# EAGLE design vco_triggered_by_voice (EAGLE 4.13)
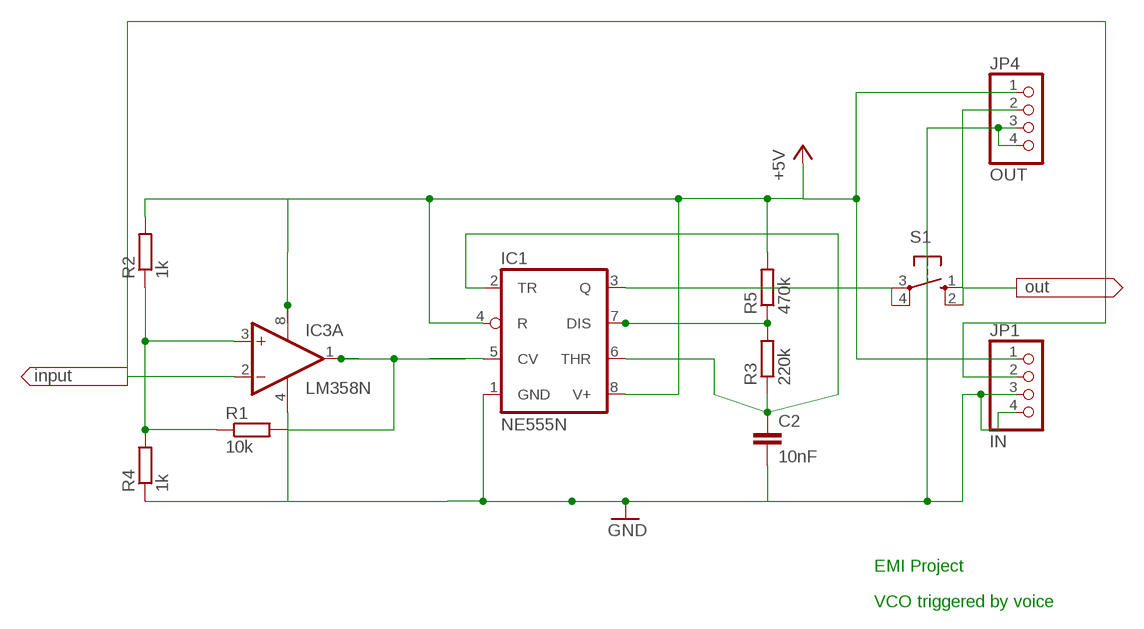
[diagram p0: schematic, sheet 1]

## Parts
C2  10nF  C-EU025-024X044  [C025-024X044]
IC1  NE555N  [DIL08]
IC3  LM358N  [DIL08]
JP1  IN  PINHD-1X4  [1X04]
JP4  OUT  PINHD-1X4  [1X04]
R1  10k  R-EU_0204/7  [0204/7]
R2  1k  R-EU_0204/7  [0204/7]
R3  220k  R-EU_0207/7  [0207/7]
R4  1k  R-EU_0204/7  [0204/7]
R5  470k  R-EU_0207/7  [0207/7]
S1  10-XX  [B3F-10XX]

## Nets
+5V: IC1.4(R) IC1.8(V+) IC3.8(P:V+) JP1.1 JP4.1 R2.2 R5.2
GND: C2.2 IC1.1(GND) IC3.4(P:V-) JP1.3 JP1.4 JP4.3 JP4.4 R4.1
N$1: IC3.3(A:+IN) R1.1 R2.1 R4.2
N$2: C2.1 IC1.2(TR) IC1.6(THR) R3.1
N$3: JP4.2 S1.1(S) S1.2(S1)
N$4: IC1.3(Q) S1.3(P) S1.4(P1)
N$6: IC1.7(DIS) R3.2 R5.1
N$7: IC3.2(A:-IN) JP1.2
N$9: IC1.5(CV) IC3.1(A:OUT) R1.2
Unconnected: IC3.5(B:+IN) IC3.6(B:-IN) IC3.7(B:OUT)

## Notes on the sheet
- EMI Project
- VCO triggered by voice

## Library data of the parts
C2 = rcl:C-EU: CAPACITOR, European symbol
IC1 = linear:*555: TIMER
IC3 = linear:LM358: OP AMP also LM158; LM258; LM2904 Source: http://cache.national.com/ds/LM/LM158.pdf
JP1 JP4 = pinhead:PINHD-1X4: PIN HEADER
R1-R5 = rcl:R-EU_: RESISTOR, European symbol
S1 = switch-omron:10-XX: OMRON SWITCH

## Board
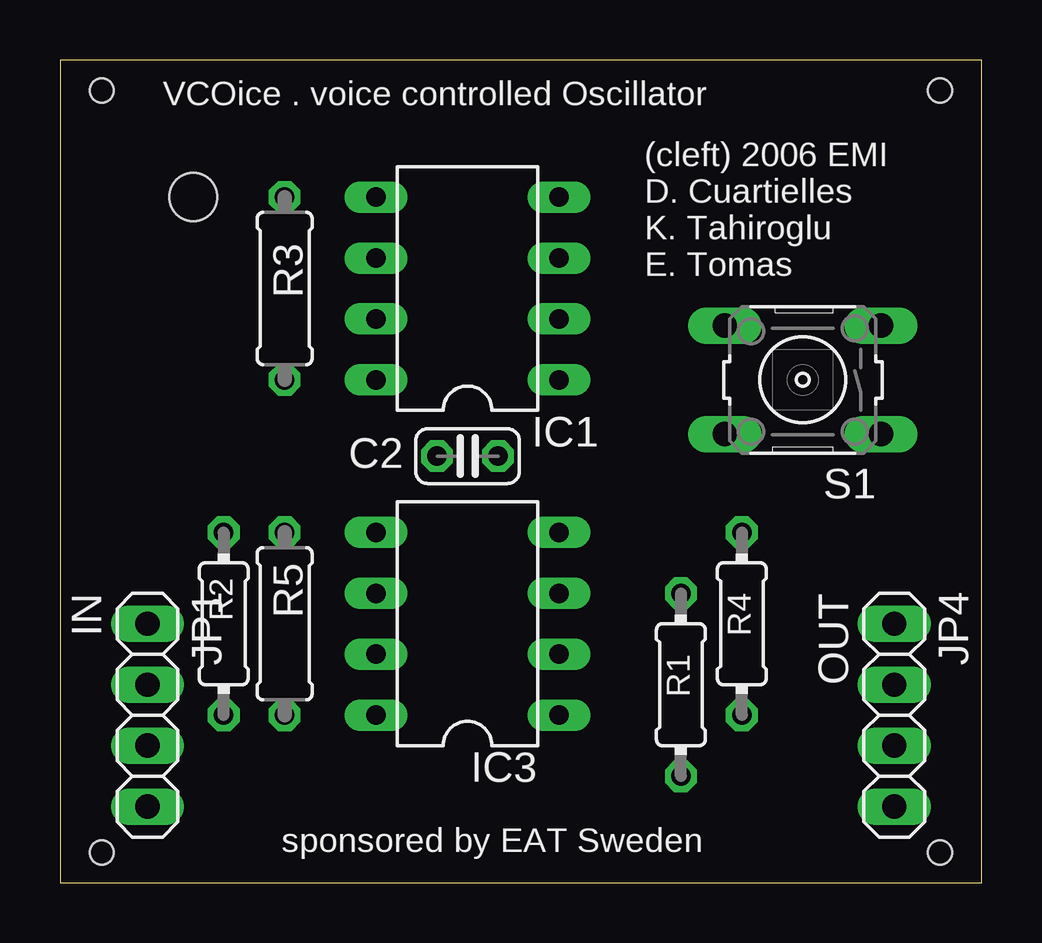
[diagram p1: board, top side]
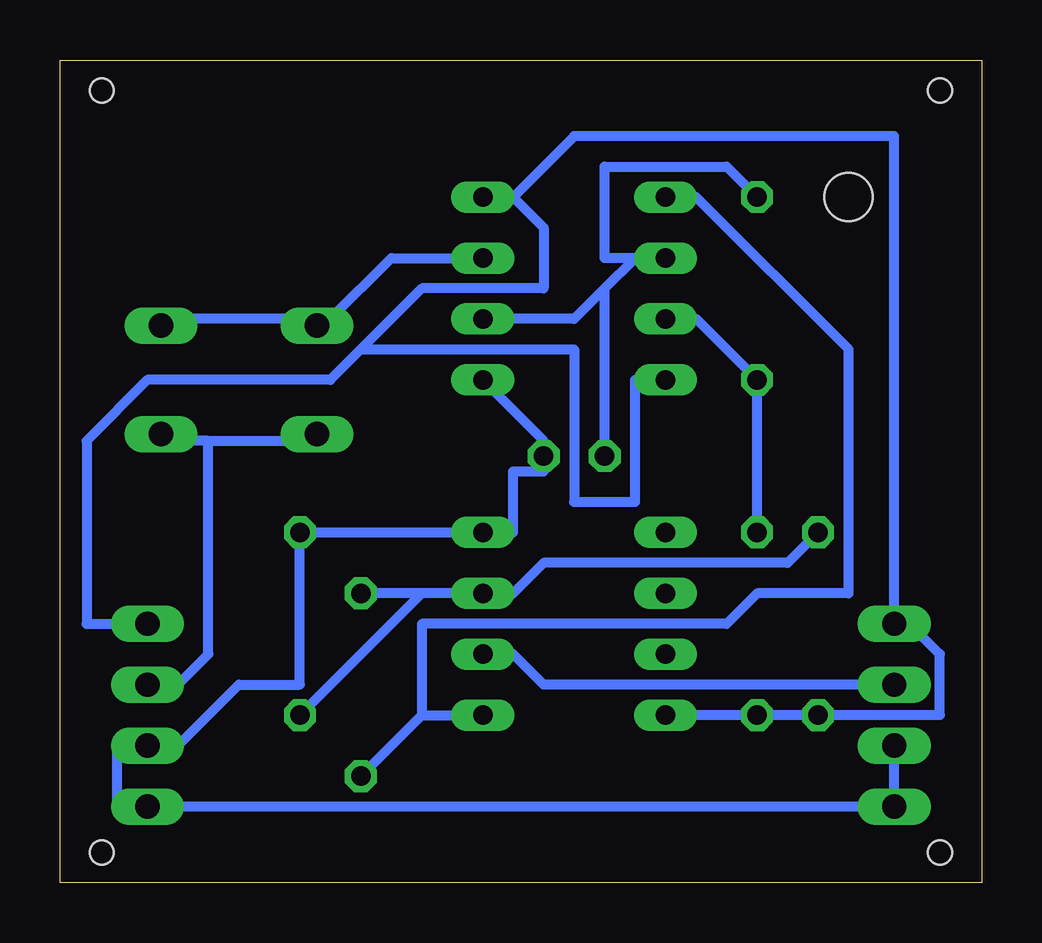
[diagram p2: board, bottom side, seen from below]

Size 38.41 x 34.28 mm. Coordinates in mm from the lower left corner, seen from the top.
Outline: 0,0 38.41,0 38.41,34.28 0,34.28 0,0
Copper layers (1*16): Top 0.035mm / dielectric 1.5mm / Bottom 0.035mm
Design rules "default": minimum track width 10mil, minimum drill 24mil, track to track 8mil, track to pad 8mil, pad to pad 8mil, via to via 8mil, smd to smd 8mil, copper to edge 40mil, drill to drill 8mil, minimum pad ring 10mil, minimum via ring 8mil, stop-mask expansion 4mil, vias tented up to drill 0mil, thermal gap 10mil
Holes 2 mm at 5.55,28.57
Holes 1 mm at 1.74,1.27 36.66,1.27 36.66,33.02 1.74,33.02

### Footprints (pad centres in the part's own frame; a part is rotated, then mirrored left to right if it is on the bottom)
C025-024X044 = drill 0.813 octagon: 1 -1.27,0; 2 1.27,0
DIL08 = drill 0.813 long: 1 -3.81,-3.81; 2 -1.27,-3.81; 3 1.27,-3.81; 4 3.81,-3.81; 5 3.81,3.81; 6 1.27,3.81; 7 -1.27,3.81; 8 -3.81,3.81
1X04 = drill 1.016 long: 1 -3.81,0; 2 -1.27,0; 3 1.27,0; 4 3.81,0
0204/7 = drill 0.813 octagon: 1 -3.81,0; 2 3.81,0
0207/7 = drill 0.813 octagon: 1 -3.81,0; 2 3.81,0
B3F-10XX = drill 1.016 long: 1 -3.251,2.261; 2 3.251,2.261; 3 -3.251,-2.261; 4 3.251,-2.261

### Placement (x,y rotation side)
C2  16.98,17.77 0 top
IC1  16.98,24.76 90 top
IC3  16.98,10.79 90 top
JP1  3.64,6.98 270 top
JP4  34.76,6.98 270 top
R1  25.87,8.25 270 top
R2  6.82,10.79 270 top
R3  9.36,24.76 270 top
R4  28.41,10.79 270 top
R5  9.36,10.79 270 top
S1  30.95,20.95 180 top

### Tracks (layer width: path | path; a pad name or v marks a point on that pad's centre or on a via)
+5V
  Bottom 0.406: IC3.8 R5.2 R2.2 1.74,6.98 1.74,9.52 3.01,10.79 JP1.1 3.64,31.11 16.98,31.11 19.52,28.57 | 25.87,22.22 16.98,22.22 16.98,15.87 14.44,15.87 14.44,20.95 IC1.8 | 25.87,22.22 27.14,20.95 34.76,20.95 37.3,18.41 37.3,10.79 JP4.1 | 19.52,28.57 18.25,27.3 18.25,24.76 23.33,24.76 25.87,22.22 | 19.52,28.57 IC1.4
GND
  Bottom 0.254: 18.25,17.14 C2.2 | 36.03,5.71 JP4.3
  Bottom 0.406: IC1.1 18.25,18.41 C2.2 | 18.25,17.14 19.52,17.14 19.52,14.6 IC3.4 R4.1 28.41,8.25 30.95,8.25 33.49,5.71 JP4.3 | JP1.3 JP1.4 JP4.4 36.03,3.17 36.03,5.71
N$1
  Bottom 0.406: 23.33,12.06 R1.1 | 23.33,12.06 IC3.3 19.52,12.06 18.25,13.33 8.09,13.33 R2.1 | 23.33,12.06 R4.2
N$2
  Bottom 0.406: 15.71,24.76 16.98,23.49 IC1.2 | 15.71,24.76 14.44,26.03 | C2.1 15.71,24.76 | R3.1 10.63,29.84 15.71,29.84 15.71,26.03 14.44,26.03 | 14.44,26.03 IC1.6
N$3
  Bottom 0.254: 33.49,8.25 JP4.2
  Bottom 0.406: 33.49,8.25 32.22,9.52 32.22,18.41 | 32.22,18.41 33.49,18.41 S1.1 | 32.22,18.41 28.41,18.41 S1.2
N$4
  Bottom 0.406: IC1.3 24.6,26.03 27.14,23.49 S1.4 28.41,23.49 33.49,23.49 S1.3
N$6
  Bottom 0.406: R5.1 R3.2 11.9,23.49 IC1.7
N$7
  Bottom 0.406: IC3.2 19.52,9.52 18.25,8.25 JP1.2
N$9
  Bottom 0.406: 23.33,6.98 R1.2 | 23.33,6.98 IC3.1 | 23.33,6.98 23.33,10.79 10.63,10.79 9.36,12.06 5.55,12.06 5.55,22.22 11.9,28.57 IC1.5

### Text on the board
tPlace: VCOice . voice controlled Oscillator | (cleft) 2006 EMI | D. Cuartielles | K. Tahiroglu | E. Tomas | sponsored by EAT Sweden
